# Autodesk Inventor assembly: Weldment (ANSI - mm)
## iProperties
Length Units: 11269
Angle Units: 11283
Time Units: 11279
Mass Units: 11290
Length Display Precision: 3
Angle Display Precision: 2
Part Number: Weldment (ANSI - mm)
Document SubType Name: Weldment
Created: 2002-06
Designer: smithga
Part Number: ex8-1
Created: 2002-11
Designer: Elise Moss
Control State: 0
Master: False
Shininess: 64.0
Angle Units: 11279
Time Units: 11290
Mass Units: 11283
Compacted: True
Density: 0.0
Volumn: 0.0
Area: 0.0
PropertySet Name: Model Information
Author: Elise Moss
